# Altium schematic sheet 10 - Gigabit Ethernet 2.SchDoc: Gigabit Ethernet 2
size A3; PageSetup: Record=PageOptions¦CenterHorizontal=True¦CenterVertical=True¦PrintScale=0.70¦XCorrection=1.00¦YCorrection=1.00¦PrintKind=0¦BorderSize=5000000¦LeftOffset=0¦BottomOffset=0¦Orientation=2¦PaperLength=4200¦PaperWidth=2970¦Scale=100¦PaperSource=7¦PrintQuality=600¦MediaType=1¦DitherType=10¦PaperKind=A4¦PrintScaleMode=1; Author: Juan Anzola; SheetNumber: 10; SheetTotal: 20
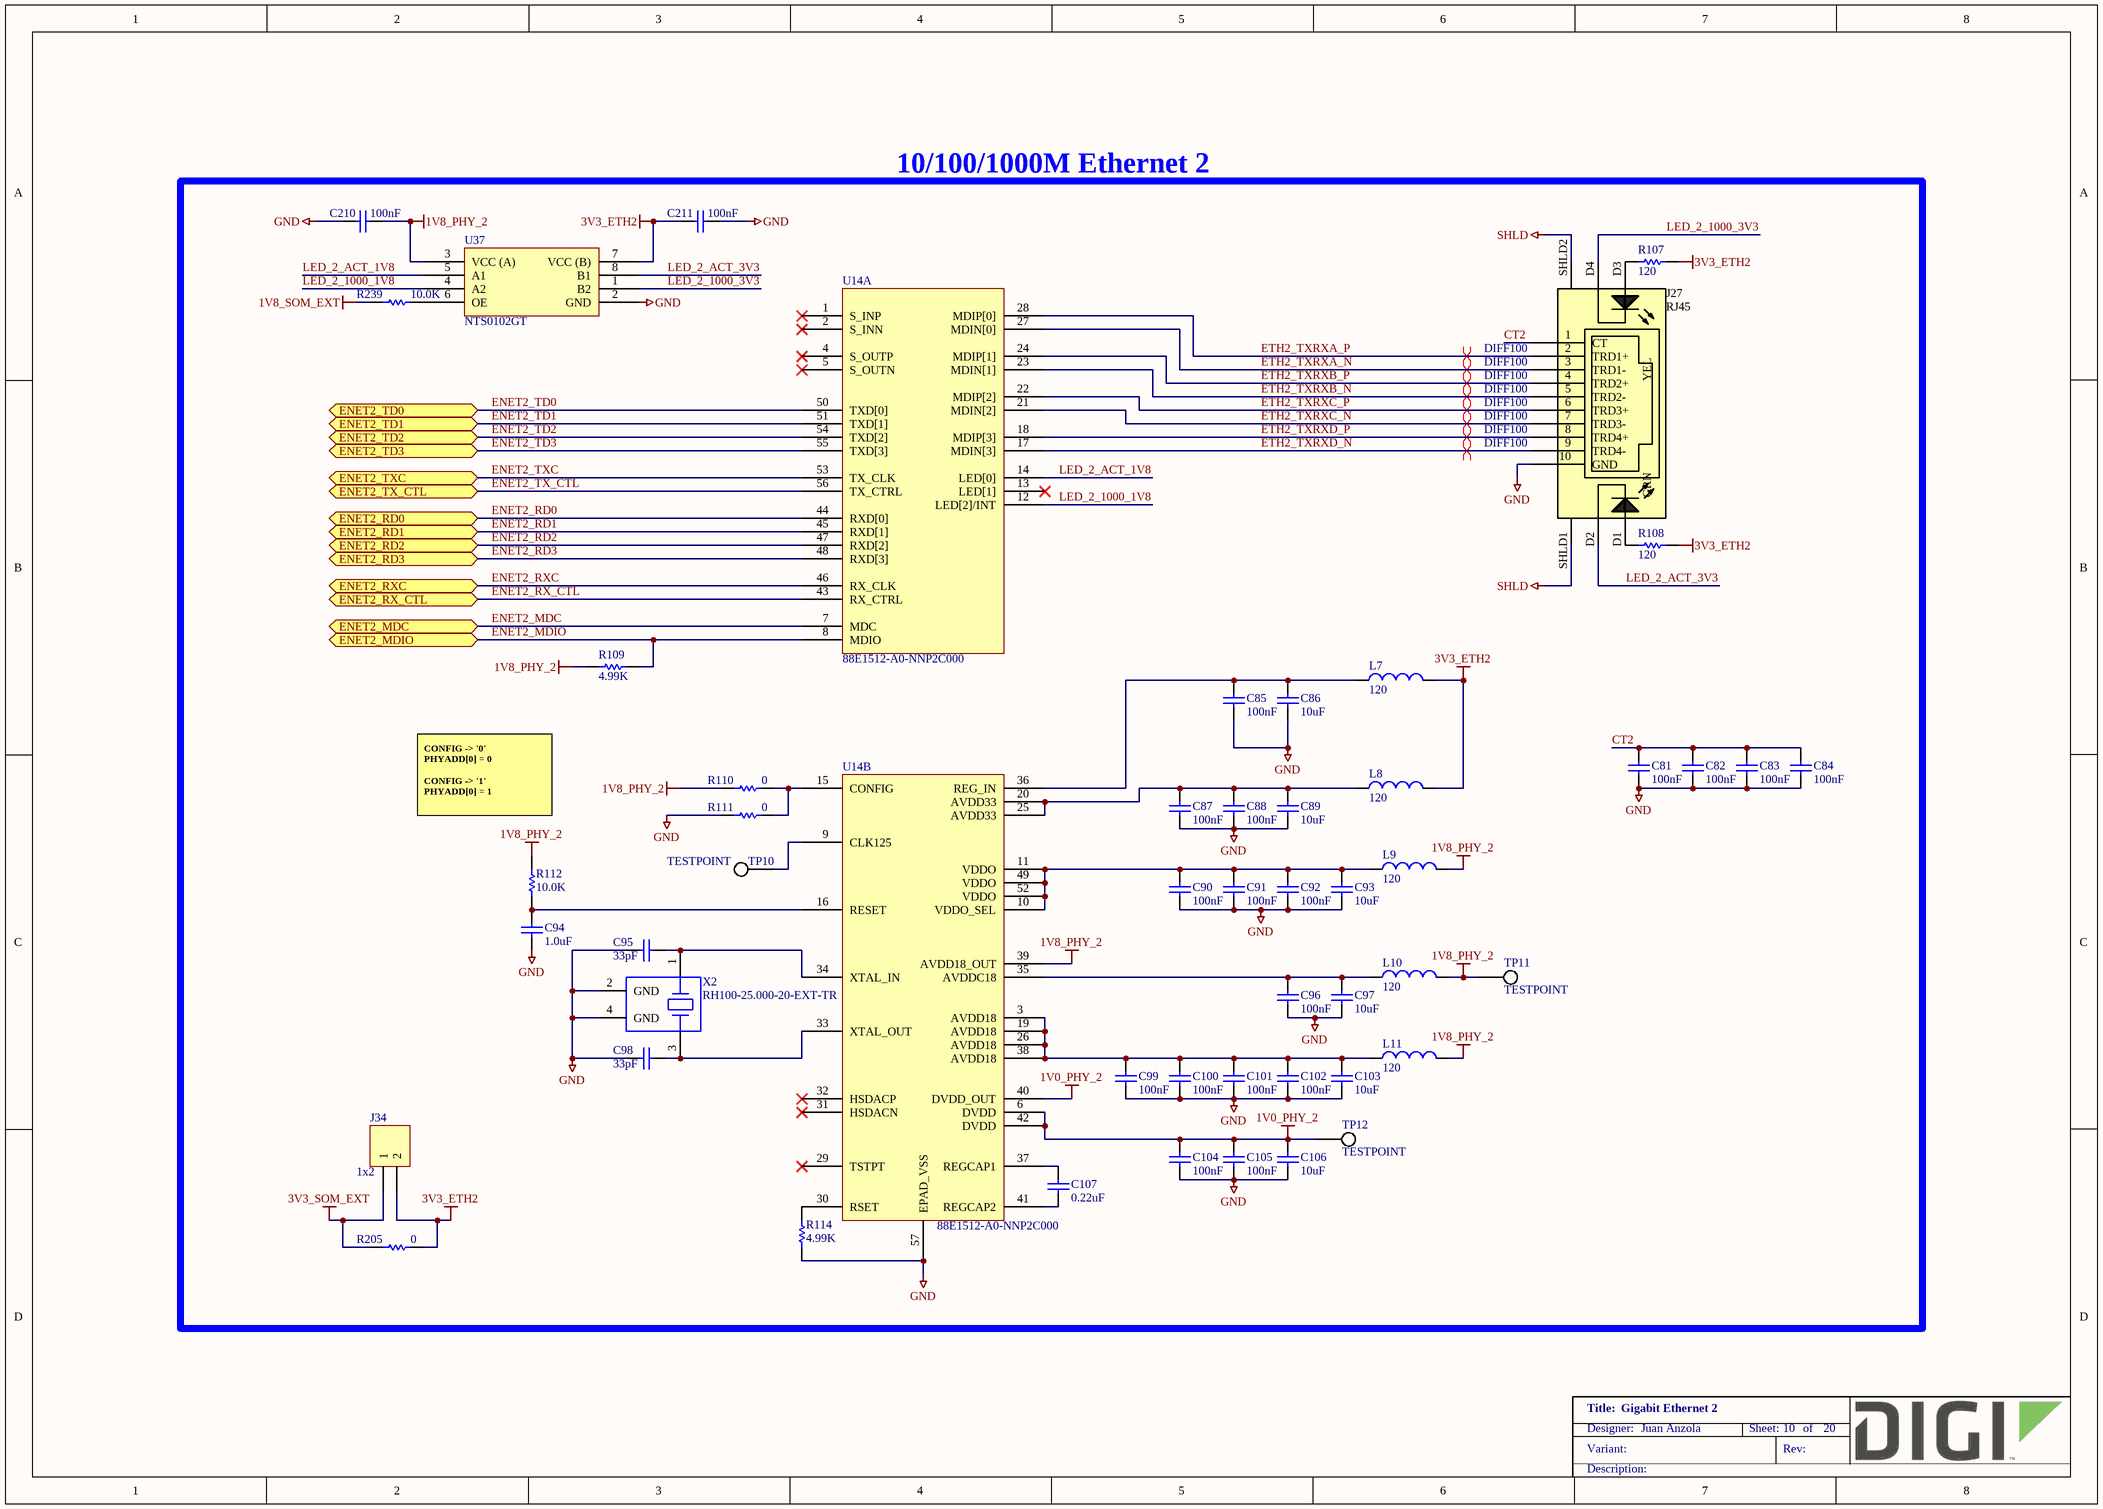
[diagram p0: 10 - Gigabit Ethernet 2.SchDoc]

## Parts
C81  100nF  [CAPC1005X55N]
C82  100nF  [CAPC1005X55N]
C83  100nF  [CAPC1005X55N]
C84  100nF  [CAPC1005X55N]
C85  100nF  [CAPC1005X55N]
C86  10uF  [CAPC2013X135N]
C87  100nF  [CAPC1005X55N]
C88  100nF  [CAPC1005X55N]
C89  10uF  [CAPC2013X135N]
C90  100nF  [CAPC1005X55N]
C91  100nF  [CAPC1005X55N]
C92  100nF  [CAPC1005X55N]
C93  10uF  [CAPC2013X135N]
C94  1.0uF  [CAPC1005X55N]
C95  33pF  [CAPC1005X55N]
C96  100nF  [CAPC1005X55N]
C97  10uF  [CAPC2013X135N]
C98  33pF  [CAPC1005X55N]
C99  100nF  [CAPC1005X55N]
C100  100nF  [CAPC1005X55N]
C101  100nF  [CAPC1005X55N]
C102  100nF  [CAPC1005X55N]
C103  10uF  [CAPC2013X135N]
C104  100nF  [CAPC1005X55N]
C105  100nF  [CAPC1005X55N]
C106  10uF  [CAPC2013X135N]
C107  0.22uF  [CAPC1005X55N]
C210  100nF  [CAPC1005X55N]
C211  100nF  [CAPC1005X55N]
J27  RJ45  [XMULTIPLE_XMG-J1B211]
J34  1x2  [FCI_68002-102HLF]
L7  120  [INDC1005X60N]
L8  120  [INDC1005X60N]
L9  120  [INDC1005X60N]
L10  120  [INDC1005X60N]
L11  120  [INDC1005X60N]
R107  120  [RESC1005X40N]
R108  120  [RESC1005X40N]
R109  4.99K  [RESC1005X40N]
R110  0  [RESC1609X55N]
R111  0  [RESC1609X55N]
R112  10.0K  [RESC1005X40N]
R114  4.99K  [RESC1005X40N]
R205  0  [RESC1609X55N]
R239  10.0K  [RESC1005X40N]
TP10  TESTPOINT  [TP0762]  (no BOM)
TP11  TESTPOINT  [TP0762]  (no BOM)
TP12  TESTPOINT  [TP0762]  (no BOM)
U14  88E1512-A0-NNP2C000  [QFN56P8mmx8mm-4.50mmPAD]  (parts A,B of 2)
U37  NTS0102GT  [PSON50P195X100X50-8N]
X2  RH100-25.000-20-EXT-TR  [OSC210P320X250X90-4N]

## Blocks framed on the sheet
10/100/1000M Ethernet 2: C81-C107 C210 C211 J27 J34 L7-L11 R107-R112 R114 R205 R239 TP10-TP12 U14 U37 X2

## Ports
ENET2_MDC (bidir), ENET2_MDIO (bidir), ENET2_RD0 (bidir), ENET2_RD1 (bidir), ENET2_RD2 (bidir), ENET2_RD3 (bidir), ENET2_RX_CTL (bidir), ENET2_RXC (bidir), ENET2_TD0 (bidir), ENET2_TD1 (bidir), ENET2_TD2 (bidir), ENET2_TD3 (bidir), ENET2_TX_CTL (bidir), ENET2_TXC (bidir)

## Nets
1V0_PHY_2: C104.2 C105.2 C106.2 TP12.1 U14.6(DVDD) U14.40(DVDD_OUT) U14.42(DVDD)
1V8_PHY_2: C210.2 L9.2 L10.2 L11.2 R109.1 R110.1 R112.2 TP11.1 U14.39(AVDD18_OUT) U37.3(VCC_(A))
1V8_SOM_EXT: R239.1
3V3_ETH2: C211.1 J34.2 L7.2 L8.2 R107.1 R108.1 R205.2 U37.7(VCC_(B))
3V3_SOM_EXT: J34.1 R205.1
GND: C81.1 C82.1 C83.1 C84.1 C85.1 C86.1 C87.1 C88.1 C89.1 C90.1 C91.1 C92.1 C93.1 C94.2 C95.1 C96.1 C97.1 C98.1 C99.1 C100.1 C101.1 C102.1 C103.1 C104.1 C105.1 C106.1 C210.1 C211.2 J27.10(GND) R111.1 R114.1 U14.57(EPAD_VSS) U37.2(GND) X2.2(GND) X2.4(GND)
SHLD: J27.SHLD1(SHLD) J27.SHLD2(SHLD)
CT2: C81.2 C82.2 C83.2 C84.2 J27.1(CT)
ENET2_MDC: U14.7(MDC) ; port ENET2_MDC
ENET2_MDIO: R109.2 U14.8(MDIO) ; port ENET2_MDIO
ENET2_RD0: U14.44(RXD[0]) ; port ENET2_RD0
ENET2_RD1: U14.45(RXD[1]) ; port ENET2_RD1
ENET2_RD2: U14.47(RXD[2]) ; port ENET2_RD2
ENET2_RD3: U14.48(RXD[3]) ; port ENET2_RD3
ENET2_RX_CTL: U14.43(RX_CTRL) ; port ENET2_RX_CTL
ENET2_RXC: U14.46(RX_CLK) ; port ENET2_RXC
ENET2_TD0: U14.50(TXD[0]) ; port ENET2_TD0
ENET2_TD1: U14.51(TXD[1]) ; port ENET2_TD1
ENET2_TD2: U14.54(TXD[2]) ; port ENET2_TD2
ENET2_TD3: U14.55(TXD[3]) ; port ENET2_TD3
ENET2_TX_CTL: U14.56(TX_CTRL) ; port ENET2_TX_CTL
ENET2_TXC: U14.53(TX_CLK) ; port ENET2_TXC
ETH2_TXRXA_N: J27.3(TRD1-) U14.27(MDIN[0])
ETH2_TXRXA_P: J27.2(TRD1+) U14.28(MDIP[0])
ETH2_TXRXB_N: J27.5(TRD2-) U14.23(MDIN[1])
ETH2_TXRXB_P: J27.4(TRD2+) U14.24(MDIP[1])
ETH2_TXRXC_N: J27.7(TRD3-) U14.21(MDIN[2])
ETH2_TXRXC_P: J27.6(TRD3+) U14.22(MDIP[2])
ETH2_TXRXD_N: J27.9(TRD4-) U14.17(MDIN[3])
ETH2_TXRXD_P: J27.8(TRD4+) U14.18(MDIP[3])
LED_2_1000_1V8: U14.12(LED[2]/INT) U37.4(A2)
LED_2_1000_3V3: J27.D4 U37.1(B2)
LED_2_ACT_1V8: U14.14(LED[0]) U37.5(A1)
LED_2_ACT_3V3: J27.D2 U37.8(B1)
NetC85_2: C85.2 C86.2 L7.1 U14.36(REG_IN)
NetC87_2: C87.2 C88.2 C89.2 L8.1 U14.20(AVDD33) U14.25(AVDD33)
NetC90_2: C90.2 C91.2 C92.2 C93.2 L9.1 U14.10(VDDO_SEL) U14.11(VDDO) U14.49(VDDO) U14.52(VDDO)
NetC94_1: C94.1 R112.1 U14.16(RESET)
NetC95_2: C95.2 U14.34(XTAL_IN) X2.1
NetC96_2: C96.2 C97.2 L10.1 U14.35(AVDDC18)
NetC98_2: C98.2 U14.33(XTAL_OUT) X2.3
NetC99_2: C99.2 C100.2 C101.2 C102.2 C103.2 L11.1 U14.3(AVDD18) U14.19(AVDD18) U14.26(AVDD18) U14.38(AVDD18)
NetC107_1: C107.1 U14.37(REGCAP1)
NetC107_2: C107.2 U14.41(REGCAP2)
NetJ27_D1: J27.D1 R108.2
NetJ27_D3: J27.D3 R107.2
NetR110_2: R110.2 R111.2 U14.15(CONFIG)
NetR114_2: R114.2 U14.30(RSET)
NetR239_2: R239.2 U37.6(OE)
NetTP10_1: TP10.1 U14.9(CLK125)

Not connected (* = marked no-connect by the designer): U14 1(S_INP)* 2(S_INN)* 4(S_OUTP)* 5(S_OUTN)* 13(LED[1])* 29(TSTPT)* 31(HSDACN)* 32(HSDACP)*

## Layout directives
differential pair; differential pair class DIFF100: ETH2_TXRXA_N, ETH2_TXRXA_P, ETH2_TXRXC_N, ETH2_TXRXC_P, ETH2_TXRXD_N, ETH2_TXRXD_P
differential pair; net class DIFF100; differential pair class DIFF100: ETH2_TXRXB_N, ETH2_TXRXB_P

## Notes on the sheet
- CONFIG -> '0'
  PHYADD[0] = 0
  CONFIG -> '1'
  PHYADD[0] = 1

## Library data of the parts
C81 C84 = 1000006: CAP 100nF 16V 10% X7R 0402; Part_Type: Capacitor; Manufacturer: Murata; Manufacturer_Part_Number: GRM155R71C104KA88D; Digi_PN: 14050552; Component_Life_Cycle_State: CAD Reviewed; Area: 0,95; Project: KITT; Tolerance: 10
C82 C83 C85 C102 C105 C210 C211 = 1000006: CAP 100nF 16V 10% X7R 0402; Part_Type: Capacitor; Manufacturer: Murata; Manufacturer_Part_Number: GRM155R71C104KA88D; Digi_PN: 14050552; Component_Life_Cycle_State: CAD Reviewed; Area: 0,95; Tolerance: 10
C86 = 1000111: CAP CER 10UF 16V 10% X5R 0805; Part_Type: Capacitor; Manufacturer: Murata; Manufacturer_Part_Number: GRM21BR61C106KE15L; Digi_PN: 14050701; Component_Life_Cycle_State: Proven; Area: 3.99; Project: Adjustable Foundation; Tolerance: 10
C87 C88 C90-C92 C96 C99-C101 C104 = 1000006: CAP 100nF 16V 10% X7R 0402; Part_Type: Capacitor; Manufacturer: Murata; Manufacturer_Part_Number: GRM155R71C104KA88D; Component_Life_Cycle_State: CAD Reviewed; Area: 0.95; Project: KITT; Tolerance: 10; Digi_PN: 14050552
C89 C93 C97 C103 C106 = 1000111: CAP CER 10UF 16V 10% X5R 0805; Part_Type: Capacitor; Manufacturer: Murata; Manufacturer_Part_Number: GRM21BR61C106KE15L; Digi_PN: 14050701; Component_Life_Cycle_State: Proven; Area: 3,99; Tolerance: 10
C94 = 1001167: CAP CER 1UF 10V 10% X5R 0402
C95 C98 = 1002646: CAP CER 33PF 50V C0G/NP0 0402; Part_Type: Capacitor; Manufacturer: Murata; Manufacturer_Part_Number: GCM1555C1H330JA16D; Digi_PN: 14050400; Component_Life_Cycle_State: Reviewed; Area: 2,12; Voltage: 50; Tolerance: 5%
C107 = 1001883: CAP CER 0.22UF 6.3V X7R 0402; Part_Type: Capacitor; Manufacturer: Taiyo Yuden; Manufacturer_Part_Number: JMK105B7224KV-F; Digi_PN: 14000067; Component_Life_Cycle_State: Reviewed; Area: 2.2; Project: Powerley Energy Bridge; Tolerance: 10%
J27 = 1002612: CONN MAGJACK 1PORT 1000 BASE-T IND; Part_Type: Connector; Manufacturer: XMultiple; Manufacturer_Part_Number: XMG-J1B2211NPA-1-DIG; Digi_PN: 18000772; Component_Life_Cycle_State: Created; Area: 339.5; Project: DIGI CC8X SOM
J34 = 1001128: CONN HEADER 2POS .100" SGL GOLD; Part_Type: Connector; Manufacturer: Samtec; Manufacturer_Part_Number: TSW-102-07-G-S; Digi_PN: 00120002; Component_Life_Cycle_State: Reviewed; Area: 12,9032
L7 = 1001175: FERRITE BEAD 120 OHM .35A 0402; Part_Type: Filter; Manufacturer: Wurth Electronics Inc; Manufacturer_Part_Number: 7427927112; Digi_PN: 21000128; Symbol: Inductor; Component_Life_Cycle_State: Reviewed; Area: 1,12; Project: CCWMX6_SBC board
L8-L11 = 1001175: FERRITE BEAD 120 OHM .35A 0402; Part_Type: Filter; Manufacturer: Wurth Electronics Inc; Manufacturer_Part_Number: 7427927112; Digi_PN: 21000128; Component_Life_Cycle_State: Reviewed; Area: 1,12
R107 R108 = 1001158: RES 120 OHM 1/16W 1% 0402 SMD; Part_Type: Resistor; Manufacturer: Yageo; Manufacturer_Part_Number: RC0402FR-07120RL; Digi_PN: 13050832; Component_Life_Cycle_State: Reviewed; Area: 0.95; Project: CCWMX6_SBC board; Note: 13051102 = Digi No. for GE WDNU
R109 R114 = 1000474: RES 4.99K OHM 1/10W 1% 0402 SMD; Part_Type: Resistor; Manufacturer: Panasonic - ECG; Manufacturer_Part_Number: ERJ-2RKF4991X; Digi_PN: 13050860; Component_Life_Cycle_State: CAD Reviewed; Area: 0,95; Power_WV_SRF: 100
R110 R111 R205 = 1000208: RES 0.0 OHM 1/10W 0603; Part_Type: Resistor; Manufacturer: Panasonic - ECG; Manufacturer_Part_Number: ERJ-3GEY0R00V; Note: 13051103 = Digi No. for GE WDNU; Digi_PN: 13050568; Component_Life_Cycle_State: Reviewed; Area: 2,5; Voltage: 75V
R112 = 1000537: RES 10.0K OHM 1/10W 1% 0402 SMD
R239 = 1000537: RES 10.0K OHM 1/10W 1% 0402 SMD; Part_Type: Resistor; Manufacturer: Panasonic - ECG; Manufacturer_Part_Number: ERJ-2RKF1002X; Digi_PN: 13051084; Component_Life_Cycle_State: CAD Reviewed; Area: 0,95; Power_WV_SRF: 100
TP10-TP12 = CAD0011: TEST POINT 30MIL PAD SMT; Component_Life_Cycle_State: Reviewed; Area: 0,58; Project: CLC
U14 = 1002866: SMIC,Gb Eth phy 0/70°C QFN-56 8x8mm; Part_Type: IC; Manufacturer: Marvell; Digi_PN: ACC-240174; Component_Life_Cycle_State: Created; Area: 64
U37 = 1002597: IC TRANSLATING TXRX 8XSON; Manufacturer: NXP Semiconductors; Manufacturer_Part_Number: NTS0102GT,115; Digi_PN: 16000138; Component_Life_Cycle_State: Reviewed; Area: 3,9
X2 = 1001497: SMCRY,25MHZ 50PPM 20PF RH100 EXT; Part_Type: Crystals-Oscillators; Manufacturer: Raltron; Digi_PN: 20000285; Component_Life_Cycle_State: Reviewed; Area: 3,2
